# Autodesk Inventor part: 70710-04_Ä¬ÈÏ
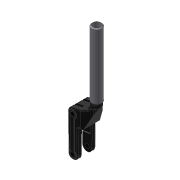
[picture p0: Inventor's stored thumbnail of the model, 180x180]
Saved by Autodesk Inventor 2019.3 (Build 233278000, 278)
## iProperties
Created: 2010-06
Part Number: 70710-04_Ä¬ÈÏ
Material: Ogólny
Document SubType Name: Modeling
Designer: CADENGINEERING4
Density: 1 g/cm^3
Appearance: Domyślna
Author: CADENGINEERING4
Revision Number: ÈÎºÎ
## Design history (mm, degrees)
feature "NONE"
feature "NONE:1"
node "Bryła1"
node "Bryła2"
